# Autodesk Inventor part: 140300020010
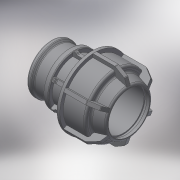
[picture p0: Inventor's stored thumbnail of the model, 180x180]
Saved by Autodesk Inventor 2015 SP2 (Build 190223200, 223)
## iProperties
Created: 2017-08
Part Number: 140300020010
Material: Generic
Description: PLASSON L.14 FEMALE ADAPTOR (SILVER) 20-1"
Document SubType Name: Modeling
Designer: KIM
Density: 1 g/cm^3
Appearance: Default
Author: KIM
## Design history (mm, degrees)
derived "140300.ipt"
feature "Solid1::140300.ipt"
tag "TaggingFeature1"
body "Solid1"
other parameters: "d2" = 54, "d4" = 15 deg, "d5" = 35.64, "d6" = 11.7612, "d9" = 30.291, "d11" = 39.3783, "d12" = 36.3492, "d13" = 42.4074, "d14" = 21, "d16" = 20.4, "d17" = 2.7, "d19" = 6.3, "d20" = 135 deg, "d21" = 6.3, "d22" = 36.3492, "d23" = 18, "d24" = 2.7, "d25" = 45, "d26" = 37.5, "d27" = 2.7, "d28" = 135 deg, "d29" = 1.62, "d31" = 1, "d44" = 0.4, "d45" = 0.6, "d46" = 150 deg, "d49" = 2.5, "d50" = 0, "d51" = 0.5, "d52" = 1, "d53" = 45 deg, "d55" = 7.244, "d56" = 2.5, "d57" = 0, "d58" = 0.6, "d61" = 360 deg, "G_" = 30.291, "l_" = 54, "l_2" = 21, "d54" = 18.11
